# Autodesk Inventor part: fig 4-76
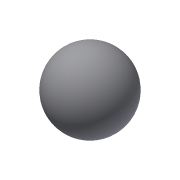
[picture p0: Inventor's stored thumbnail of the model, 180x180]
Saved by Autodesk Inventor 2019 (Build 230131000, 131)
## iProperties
Created: 2012-07
Part Number: fig 4-76
Material: Generic
Document SubType Name: Modeling
Designer: CADCIM
Density: 1 g/cm^3
Appearance: Default
Author: CADCIM
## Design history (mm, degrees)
sketch "Sketch1"
  geometry: L1 (7.807, -5.174)-(-7.807, 5.174); A1 r 9.366 centre (0, 0) between (7.807, -5.174) and (-7.807, 5.174)
  constraints: 2 end point, 2 point on circle, 1 centre point, 1 midpoint
  dimensions: "d0" = 90 deg dimension on A1.centre A1 L1.start L1.end L1
revolve "Revolution1" sketch "Sketch1" stored, may be unused: angle "d0" = 90 deg
body "Solid1"
